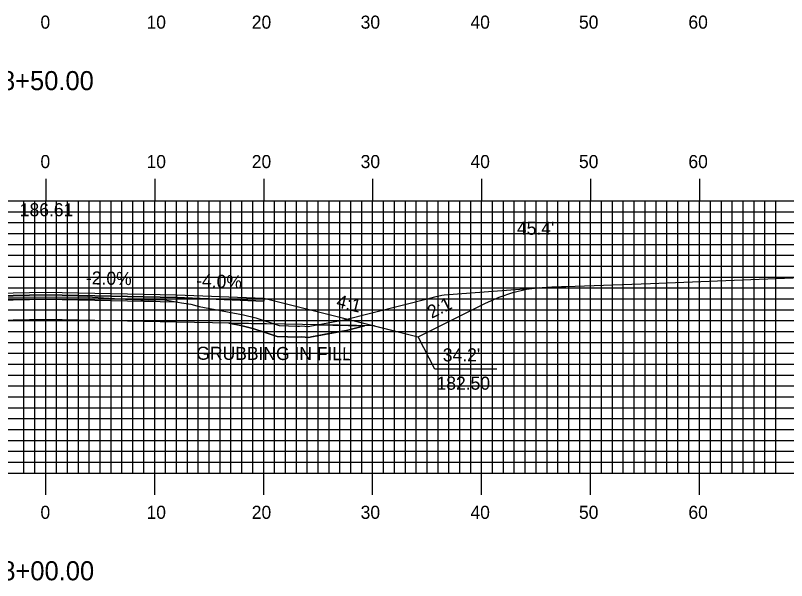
# Model space of a CAD drawing. Extents: x 1823966 to 1824309, y 442591 to 442811.
# Drawn here: x 1824129 to 1824199.8, y 442641.7 to 442693.6 of the extents above; entities that cross this region are included whole.
import ezdxf

# ---------------------------------------------------------------- set-up
doc = ezdxf.new("R2010")
doc.units = 0
for name, color, linetype in [('ANNOTATION', 7, 'Continuous'), ('D_Roadway_Centerline', 7, 'Continuous'), ('D_Roadway_Centerline_Text', 7, 'Continuous'), ('D_Roadway_Edge_Shoulder', 7, 'Continuous'), ('D_Roadway_Edge_TW', 7, 'Continuous'), ('D_Roadway_Pavement', 7, 'Continuous'), ('D_Roadway_SlopeLines', 7, 'Continuous'), ('D_Roadway_SubGrade', 7, 'Continuous'), ('D_Text_Standard', 7, 'Continuous'), ('GRUBBING IN FILL', 7, 'Continuous'), ('H_V ANNOTATION', 7, 'Continuous'), ('MAJOR', 7, 'Continuous'), ('MINOR', 7, 'Continuous'), ('S_Roadway_Centerline', 7, 'Continuous')]:
    doc.layers.add(name, color=color, linetype=linetype)

msp = doc.modelspace()

# ---------------------------------------------------------------- linework, layer by layer
at = {"layer": 'ANNOTATION'}
msp.add_lwpolyline([(1824173.216, 442661.116), (1824167.524, 442661.116), (1824165.996, 442664.092)], dxfattribs=at)
at = {"layer": 'D_Roadway_Centerline'}
msp.add_lwpolyline([(1824101.648, 442665.092), (1824110.485, 442667.301), (1824111.822, 442667.635), (1824119.822, 442667.955), (1824131.822, 442668.195), (1824143.822, 442667.955), (1824151.822, 442667.635), (1824161.996, 442665.092), (1824165.996, 442664.092), (1824172.175, 442667.181), (1824173.425, 442667.74), (1824174.675, 442668.166), (1824175.925, 442668.461), (1824177.175, 442668.623)], dxfattribs=at)
at = {"layer": 'D_Roadway_Edge_Shoulder'}
msp.add_lwpolyline([(1824143.822, 442667.955), (1824151.822, 442667.635), (1824151.822, 442667.385), (1824143.822, 442667.705)], close=True, dxfattribs=at)
at = {"layer": 'D_Roadway_Edge_TW'}
msp.add_lwpolyline([(1824119.822, 442667.705), (1824119.822, 442667.955), (1824131.822, 442668.195), (1824143.822, 442667.955), (1824143.822, 442667.705), (1824131.822, 442667.945)], close=True, dxfattribs=at)
at = {"layer": 'D_Roadway_Pavement'}
msp.add_lwpolyline([(1824119.822, 442667.288), (1824119.822, 442667.705), (1824131.822, 442667.945), (1824143.822, 442667.705), (1824143.822, 442667.288), (1824131.822, 442667.528)], close=True, dxfattribs=at)
at = {"layer": 'D_Roadway_SlopeLines'}
for points in [[(1824165.996, 442664.092), (1824172.175, 442667.181), (1824173.425, 442667.74), (1824174.675, 442668.166), (1824175.925, 442668.461), (1824177.175, 442668.623)], [(1824151.822, 442667.635), (1824165.996, 442664.092)]]:
    msp.add_lwpolyline(points, dxfattribs=at)
at = {"layer": 'D_Roadway_SubGrade'}
msp.add_lwpolyline([(1824119.822, 442665.455), (1824101.648, 442665.092), (1824111.822, 442667.635), (1824111.822, 442667.385), (1824119.822, 442667.705), (1824131.822, 442667.945), (1824143.822, 442667.705), (1824151.822, 442667.385), (1824151.822, 442667.635), (1824161.996, 442665.092), (1824143.822, 442665.455), (1824131.822, 442665.695)], close=True, dxfattribs=at)
at = {"layer": 'GRUBBING IN FILL'}
msp.add_lwpolyline([(1824148.612, 442665.359), (1824149.739, 442665.148), (1824150.821, 442664.868), (1824153.075, 442664.132), (1824154.951, 442664.074), (1824155.261, 442664.091), (1824155.969, 442664.051), (1824156.223, 442664.093), (1824159.432, 442664.693), (1824161.088, 442665.11)], dxfattribs=at)
msp.add_lwpolyline([(1824148.612, 442665.359), (1824149.739, 442665.148), (1824150.821, 442664.868), (1824153.075, 442664.132), (1824154.951, 442664.074), (1824155.261, 442664.091), (1824155.969, 442664.051), (1824156.223, 442664.093), (1824159.432, 442664.693), (1824161.088, 442665.11)], dxfattribs=at)
msp.add_lwpolyline([(1824148.612, 442665.359), (1824152.794, 442665.276), (1824153.249, 442665.127), (1824154.094, 442665.101), (1824154.939, 442665.075), (1824155.1, 442665.083), (1824155.261, 442665.092), (1824155.588, 442665.074), (1824155.915, 442665.056), (1824156.691, 442665.198), (1824161.088, 442665.11), (1824159.432, 442664.693), (1824157.828, 442664.393), (1824156.223, 442664.093), (1824155.969, 442664.051), (1824155.615, 442664.071), (1824155.261, 442664.091), (1824154.951, 442664.074), (1824154.013, 442664.103), (1824153.075, 442664.132), (1824151.948, 442664.5), (1824150.821, 442664.868), (1824149.739, 442665.148)], close=True, dxfattribs=at)
msp.add_lwpolyline([(1824148.612, 442665.359), (1824152.794, 442665.276), (1824153.249, 442665.127), (1824154.094, 442665.101), (1824154.939, 442665.075), (1824155.1, 442665.083), (1824155.261, 442665.092), (1824155.588, 442665.074), (1824155.915, 442665.056), (1824156.691, 442665.198), (1824161.088, 442665.11), (1824159.432, 442664.693), (1824157.828, 442664.393), (1824156.223, 442664.093), (1824155.969, 442664.051), (1824155.615, 442664.071), (1824155.261, 442664.091), (1824154.951, 442664.074), (1824154.013, 442664.103), (1824153.075, 442664.132), (1824151.948, 442664.5), (1824150.821, 442664.868), (1824149.739, 442665.148)], close=True, dxfattribs=at)
at = {"layer": 'MAJOR'}
for p, q in [((1824131.822, 442678.592), (1824131.822, 442676.588)), ((1824141.822, 442678.592), (1824141.822, 442676.588)), ((1824151.822, 442678.592), (1824151.822, 442676.588)), ((1824161.822, 442678.592), (1824161.822, 442676.588)), ((1824171.822, 442678.592), (1824171.822, 442676.588)), ((1824181.822, 442678.592), (1824181.822, 442676.588)), ((1824191.822, 442678.592), (1824191.822, 442676.588)), ((1823991.822, 442676.588), (1824271.822, 442676.588)), ((1823991.822, 442676.588), (1824271.822, 442676.588)), ((1824131.822, 442651.588), (1824131.822, 442676.588)), ((1824141.822, 442651.588), (1824141.822, 442676.588)), ((1824151.822, 442651.588), (1824151.822, 442676.588)), ((1824161.822, 442651.588), (1824161.822, 442676.588)), ((1824171.822, 442651.588), (1824171.822, 442676.588)), ((1824181.822, 442651.588), (1824181.822, 442676.588)), ((1824191.822, 442651.588), (1824191.822, 442676.588)), ((1823991.822, 442671.588), (1824271.822, 442671.588)), ((1823991.822, 442666.588), (1824271.822, 442666.588)), ((1823991.822, 442661.588), (1824271.822, 442661.588)), ((1823991.822, 442656.588), (1824271.822, 442656.588)), ((1823991.822, 442651.588), (1824271.822, 442651.588)), ((1823991.822, 442651.588), (1824271.822, 442651.588)), ((1824131.822, 442649.584), (1824131.822, 442651.588)), ((1824141.822, 442649.584), (1824141.822, 442651.588)), ((1824151.822, 442649.584), (1824151.822, 442651.588)), ((1824161.822, 442649.584), (1824161.822, 442651.588)), ((1824171.822, 442649.584), (1824171.822, 442651.588)), ((1824181.822, 442649.584), (1824181.822, 442651.588)), ((1824191.822, 442649.584), (1824191.822, 442651.588))]:
    msp.add_line(p, q, dxfattribs=at)
at = {"layer": 'MINOR'}
for p, q in [((1824129.822, 442651.588), (1824129.822, 442676.588)), ((1824130.822, 442651.588), (1824130.822, 442676.588)), ((1824132.822, 442651.588), (1824132.822, 442676.588)), ((1824133.822, 442651.588), (1824133.822, 442676.588)), ((1824134.822, 442651.588), (1824134.822, 442676.588)), ((1824135.822, 442651.588), (1824135.822, 442676.588)), ((1824136.822, 442651.588), (1824136.822, 442676.588)), ((1824137.822, 442651.588), (1824137.822, 442676.588)), ((1824138.822, 442651.588), (1824138.822, 442676.588)), ((1824139.822, 442651.588), (1824139.822, 442676.588)), ((1824140.822, 442651.588), (1824140.822, 442676.588)), ((1824142.822, 442651.588), (1824142.822, 442676.588)), ((1824143.822, 442651.588), (1824143.822, 442676.588)), ((1824144.822, 442651.588), (1824144.822, 442676.588)), ((1824145.822, 442651.588), (1824145.822, 442676.588)), ((1824146.822, 442651.588), (1824146.822, 442676.588)), ((1824147.822, 442651.588), (1824147.822, 442676.588)), ((1824148.822, 442651.588), (1824148.822, 442676.588)), ((1824149.822, 442651.588), (1824149.822, 442676.588)), ((1824150.822, 442651.588), (1824150.822, 442676.588)), ((1824152.822, 442651.588), (1824152.822, 442676.588)), ((1824153.822, 442651.588), (1824153.822, 442676.588)), ((1824154.822, 442651.588), (1824154.822, 442676.588)), ((1824155.822, 442651.588), (1824155.822, 442676.588)), ((1824156.822, 442651.588), (1824156.822, 442676.588)), ((1824157.822, 442651.588), (1824157.822, 442676.588)), ((1824158.822, 442651.588), (1824158.822, 442676.588)), ((1824159.822, 442651.588), (1824159.822, 442676.588)), ((1824160.822, 442651.588), (1824160.822, 442676.588)), ((1824162.822, 442651.588), (1824162.822, 442676.588)), ((1824163.822, 442651.588), (1824163.822, 442676.588)), ((1824164.822, 442651.588), (1824164.822, 442676.588)), ((1824165.822, 442651.588), (1824165.822, 442676.588)), ((1824166.822, 442651.588), (1824166.822, 442676.588)), ((1824167.822, 442651.588), (1824167.822, 442676.588)), ((1824168.822, 442651.588), (1824168.822, 442676.588)), ((1824169.822, 442651.588), (1824169.822, 442676.588)), ((1824170.822, 442651.588), (1824170.822, 442676.588)), ((1824172.822, 442651.588), (1824172.822, 442676.588)), ((1824173.822, 442651.588), (1824173.822, 442676.588)), ((1824174.822, 442651.588), (1824174.822, 442676.588)), ((1824175.822, 442651.588), (1824175.822, 442676.588)), ((1824176.822, 442651.588), (1824176.822, 442676.588)), ((1824177.822, 442651.588), (1824177.822, 442676.588)), ((1824178.822, 442651.588), (1824178.822, 442676.588)), ((1824179.822, 442651.588), (1824179.822, 442676.588)), ((1824180.822, 442651.588), (1824180.822, 442676.588)), ((1824182.822, 442651.588), (1824182.822, 442676.588)), ((1824183.822, 442651.588), (1824183.822, 442676.588)), ((1824184.822, 442651.588), (1824184.822, 442676.588)), ((1824185.822, 442651.588), (1824185.822, 442676.588)), ((1824186.822, 442651.588), (1824186.822, 442676.588)), ((1824187.822, 442651.588), (1824187.822, 442676.588)), ((1824188.822, 442651.588), (1824188.822, 442676.588)), ((1824189.822, 442651.588), (1824189.822, 442676.588)), ((1824190.822, 442651.588), (1824190.822, 442676.588)), ((1824192.822, 442651.588), (1824192.822, 442676.588)), ((1824193.822, 442651.588), (1824193.822, 442676.588)), ((1824194.822, 442651.588), (1824194.822, 442676.588)), ((1824195.822, 442651.588), (1824195.822, 442676.588)), ((1824196.822, 442651.588), (1824196.822, 442676.588)), ((1824197.822, 442651.588), (1824197.822, 442676.588)), ((1824198.822, 442651.588), (1824198.822, 442676.588)), ((1823991.822, 442675.588), (1824271.822, 442675.588)), ((1823991.822, 442674.588), (1824271.822, 442674.588)), ((1823991.822, 442673.588), (1824271.822, 442673.588)), ((1823991.822, 442672.588), (1824271.822, 442672.588)), ((1823991.822, 442670.588), (1824271.822, 442670.588)), ((1823991.822, 442669.588), (1824271.822, 442669.588)), ((1823991.822, 442668.588), (1824271.822, 442668.588)), ((1823991.822, 442667.588), (1824271.822, 442667.588)), ((1823991.822, 442665.588), (1824271.822, 442665.588)), ((1823991.822, 442664.588), (1824271.822, 442664.588)), ((1823991.822, 442663.588), (1824271.822, 442663.588)), ((1823991.822, 442662.588), (1824271.822, 442662.588)), ((1823991.822, 442660.588), (1824271.822, 442660.588)), ((1823991.822, 442659.588), (1824271.822, 442659.588)), ((1823991.822, 442658.588), (1824271.822, 442658.588)), ((1823991.822, 442657.588), (1824271.822, 442657.588)), ((1823991.822, 442655.588), (1824271.822, 442655.588)), ((1823991.822, 442654.588), (1824271.822, 442654.588)), ((1823991.822, 442653.588), (1824271.822, 442653.588)), ((1823991.822, 442652.588), (1824271.822, 442652.588))]:
    msp.add_line(p, q, dxfattribs=at)
at = {"layer": 'S_Roadway_Centerline'}
msp.add_lwpolyline([(1824124.823, 442667.736), (1824135.617, 442667.754), (1824139.151, 442667.546), (1824141.243, 442667.473), (1824142.589, 442667.522), (1824144.278, 442667.21), (1824145.131, 442667.092), (1824145.909, 442666.883), (1824149.957, 442666.125), (1824151.101, 442665.828), (1824153.249, 442665.127), (1824154.939, 442665.075), (1824155.261, 442665.092), (1824155.915, 442665.056), (1824156.05, 442665.078), (1824159.218, 442665.67), (1824167.078, 442667.649), (1824167.645, 442667.798), (1824168.158, 442667.925), (1824168.393, 442667.95), (1824177.763, 442668.668), (1824178.25, 442668.679), (1824178.661, 442668.692), (1824178.935, 442668.7), (1824179.153, 442668.707), (1824179.542, 442668.723), (1824187.327, 442669.004), (1824208.053, 442669.834)], dxfattribs=at)

# ---------------------------------------------------------------- texts
at = {"layer": 'ANNOTATION'}
for s, rotation, p in [('-2.0%', 358.85424, (1824135.508, 442668.922)), ('-4.0%', 357.70939, (1824145.613, 442668.685)), ('4:1', 345.96376, (1824158.415, 442666.849)), ('2:1', 26.56505, (1824167.23, 442665.745))]:
    msp.add_text(s, height=1.2, rotation=rotation, dxfattribs=at).set_placement(p)
for s, p in [("34.2'", (1824168.259, 442661.842)), ('182.50', (1824167.686, 442659.242))]:
    msp.add_text(s, height=1.2, dxfattribs=at).set_placement(p)
at = {"layer": 'D_Roadway_Centerline'}
for s, p in [('C', (1824131.817, 442668.195)), ('L', (1824131.822, 442668.188))]:
    msp.add_text(s, height=0.0146, dxfattribs=at).set_placement(p)
at = {"layer": 'D_Roadway_Centerline_Text'}
msp.add_text('186.61', height=1.2, dxfattribs=at).set_placement((1824129.446, 442675.168))
at = {"layer": 'D_Text_Standard'}
msp.add_text("45.4'", height=1.2, dxfattribs=at).set_placement((1824175.061, 442673.467))
at = {"layer": 'GRUBBING IN FILL'}
msp.add_text('GRUBBING IN FILL', height=1.2, rotation=359.80532, dxfattribs=at).set_placement((1824145.641, 442661.992))
at = {"layer": 'H_V ANNOTATION'}
for s, height, p in [('0', 1.2, (1824131.34, 442692.388)), ('10', 1.2, (1824141.072, 442692.388)), ('20', 1.2, (1824150.73, 442692.388)), ('30', 1.2, (1824160.719, 442692.388)), ('40', 1.2, (1824170.794, 442692.388)), ('50', 1.2, (1824180.751, 442692.388)), ('60', 1.2, (1824190.794, 442692.388)), ('338+50.00', 1.75, (1824125.111, 442686.744)), ('0', 1.2, (1824131.34, 442679.588)), ('10', 1.2, (1824141.072, 442679.588)), ('20', 1.2, (1824150.73, 442679.588)), ('30', 1.2, (1824160.719, 442679.588)), ('40', 1.2, (1824170.794, 442679.588)), ('50', 1.2, (1824180.751, 442679.588)), ('60', 1.2, (1824190.794, 442679.588)), ('0', 1.2, (1824131.34, 442647.388)), ('10', 1.2, (1824141.072, 442647.388)), ('20', 1.2, (1824150.73, 442647.388)), ('30', 1.2, (1824160.719, 442647.388)), ('40', 1.2, (1824170.794, 442647.388)), ('50', 1.2, (1824180.751, 442647.388)), ('60', 1.2, (1824190.794, 442647.388)), ('338+00.00', 1.75, (1824125.142, 442641.744))]:
    msp.add_text(s, height=height, dxfattribs=at).set_placement(p)

doc.saveas('drawing.dxf')
